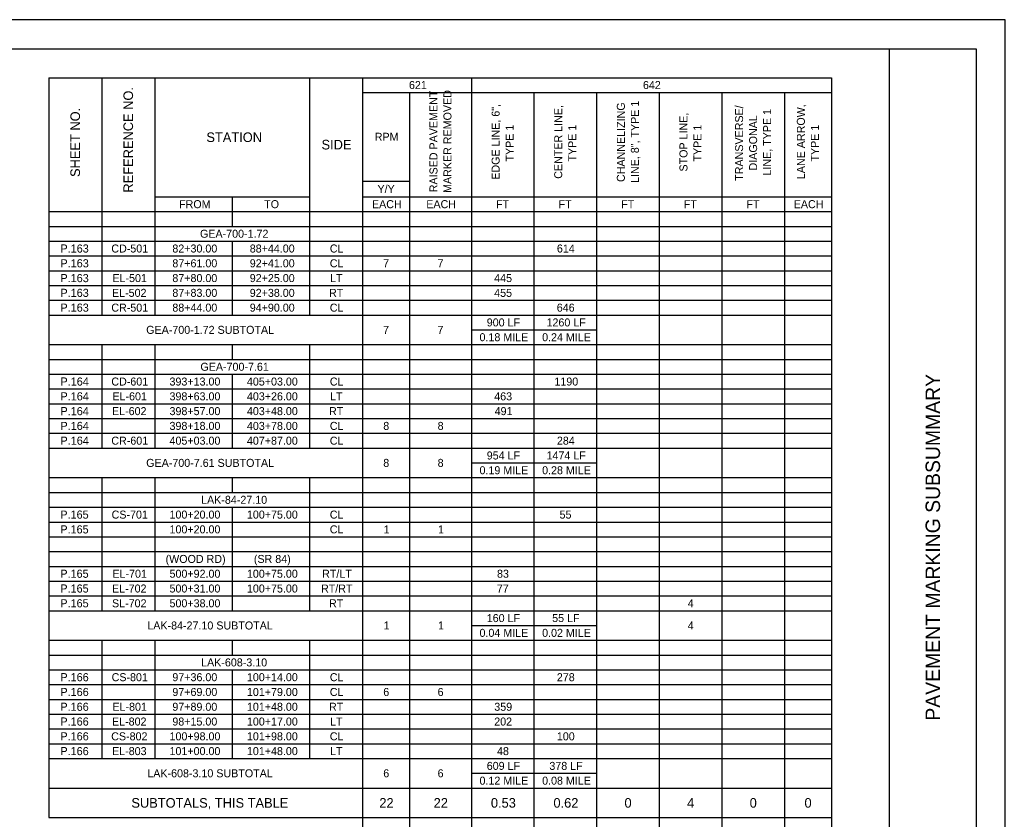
# Model space of a CAD drawing. Extents: x 0 to 34, y 0 to 22.
# Drawn here: x 17 to 34, y 8.21 to 22 of the extents above; entities that cross this region are included whole.
import ezdxf

# ---------------------------------------------------------------- set-up
doc = ezdxf.new("R2010")
doc.units = 0
for name, color, linetype in [('SH_Border', 7, 'Continuous'), ('SH_Cut_Line', 7, 'Continuous'), ('SH_Data', 7, 'Continuous'), ('SH_Text', 7, 'Continuous')]:
    doc.layers.add(name, color=color, linetype=linetype)

msp = doc.modelspace()

# ---------------------------------------------------------------- linework, layer by layer
at = {"layer": 'SH_Border'}
msp.add_line((32, 0.5), (32, 21.5), dxfattribs=at)
msp.add_lwpolyline([(1.5, 21.5), (33.5, 21.5), (33.5, 0.5), (1.5, 0.5)], close=True, dxfattribs=at)
at = {"layer": 'SH_Cut_Line'}
msp.add_lwpolyline([(0, 0), (34, 0), (34, 22), (0, 22)], close=True, dxfattribs=at)
at = {"layer": 'SH_Text'}
for p, q in [((17.5, 21), (31, 21)), ((17.5, 21), (17.5, 18.69)), ((18.415, 21), (18.415, 18.69)), ((19.33, 21), (19.33, 18.69)), ((22, 21), (22, 18.69)), ((22.915, 21), (22.915, 18.69)), ((24.79, 21), (24.79, 18.69)), ((31, 21), (31, 18.69)), ((22.915, 20.745), (31, 20.745)), ((23.725, 20.745), (23.725, 18.69)), ((25.87, 20.745), (25.87, 18.69)), ((26.95, 20.745), (26.95, 18.69)), ((28.03, 20.745), (28.03, 18.69)), ((29.11, 20.745), (29.11, 18.69)), ((30.19, 20.745), (30.19, 18.69)), ((22.915, 19.215), (23.725, 19.215)), ((19.33, 18.945), (22, 18.945)), ((20.665, 18.945), (20.665, 18.69)), ((22.915, 18.945), (31, 18.945)), ((17.5, 18.69), (31, 18.69)), ((17.5, 18.69), (31, 18.69)), ((17.5, 18.69), (17.5, 8.235)), ((18.415, 18.69), (18.415, 16.905)), ((19.33, 18.69), (19.33, 16.905)), ((20.665, 18.69), (20.665, 18.435)), ((22, 18.69), (22, 16.905)), ((22.915, 18.69), (22.915, 6.435)), ((23.725, 18.69), (23.725, 6.435)), ((24.79, 18.69), (24.79, 6.435)), ((25.87, 18.69), (25.87, 6.435)), ((26.95, 18.69), (26.95, 6.435)), ((28.03, 18.69), (28.03, 6.435)), ((29.11, 18.69), (29.11, 6.435)), ((30.19, 18.69), (30.19, 6.435)), ((31, 18.69), (31, 6.435)), ((17.5, 18.435), (31, 18.435)), ((17.5, 18.18), (31, 18.18)), ((20.665, 18.18), (20.665, 16.905)), ((17.5, 17.925), (31, 17.925)), ((17.5, 17.67), (31, 17.67)), ((17.5, 17.415), (31, 17.415)), ((17.5, 17.16), (31, 17.16)), ((17.5, 16.905), (31, 16.905)), ((24.79, 16.65), (26.95, 16.65)), ((17.5, 16.395), (31, 16.395)), ((18.415, 16.395), (18.415, 14.61)), ((19.33, 16.395), (19.33, 14.61)), ((20.665, 16.395), (20.665, 16.14)), ((22, 16.395), (22, 14.61)), ((17.5, 16.14), (31, 16.14)), ((17.5, 15.885), (31, 15.885)), ((20.665, 15.885), (20.665, 14.61)), ((17.5, 15.63), (31, 15.63)), ((17.5, 15.375), (31, 15.375)), ((17.5, 15.12), (31, 15.12)), ((17.5, 14.865), (31, 14.865)), ((17.5, 14.61), (31, 14.61)), ((24.79, 14.355), (26.95, 14.355)), ((17.5, 14.1), (31, 14.1)), ((18.415, 14.1), (18.415, 11.805)), ((19.33, 14.1), (19.33, 11.805)), ((20.665, 14.1), (20.665, 13.845)), ((22, 14.1), (22, 11.805)), ((17.5, 13.845), (31, 13.845)), ((17.5, 13.59), (31, 13.59)), ((20.665, 13.59), (20.665, 11.805)), ((17.5, 13.335), (31, 13.335)), ((17.5, 13.08), (31, 13.08)), ((17.5, 12.825), (31, 12.825)), ((17.5, 12.57), (31, 12.57)), ((17.5, 12.315), (31, 12.315)), ((17.5, 12.06), (31, 12.06)), ((17.5, 11.805), (31, 11.805)), ((24.79, 11.55), (26.95, 11.55)), ((17.5, 11.295), (31, 11.295)), ((18.415, 11.295), (18.415, 9.255)), ((19.33, 11.295), (19.33, 9.255)), ((20.665, 11.295), (20.665, 11.04)), ((22, 11.295), (22, 9.255)), ((17.5, 11.04), (31, 11.04)), ((17.5, 10.785), (31, 10.785)), ((20.665, 10.785), (20.665, 9.255)), ((17.5, 10.53), (31, 10.53)), ((17.5, 10.275), (31, 10.275)), ((17.5, 10.02), (31, 10.02)), ((17.5, 9.765), (31, 9.765)), ((17.5, 9.51), (31, 9.51)), ((17.5, 9.255), (31, 9.255)), ((24.79, 9), (26.95, 9)), ((17.5, 8.745), (31, 8.745)), ((17.5, 8.235), (22.915, 8.235)), ((22.915, 8.235), (31, 8.235))]:
    msp.add_line(p, q, dxfattribs=at)

# ---------------------------------------------------------------- texts
at = {"layer": 'SH_Data'}
msp.add_text('PAVEMENT MARKING SUBSUMMARY', height=0.25, rotation=90, dxfattribs=at).set_placement((32.875, 9.908))
at = {"layer": 'SH_Text'}
for s, height, p in [('621', 0.138, (23.714, 20.804)), ('642', 0.138, (27.75, 20.804)), ('STATION', 0.1656, (20.22, 19.89)), ('SIDE', 0.1656, (22.206, 19.762)), ('RPM', 0.138, (23.124, 19.911)), ('Y/Y', 0.138, (23.171, 19.011)), ('FROM', 0.138, (19.749, 18.749)), ('TO', 0.138, (21.217, 18.749)), ('EACH', 0.138, (23.076, 18.749)), ('EACH', 0.138, (24.013, 18.749)), ('FT', 0.138, (25.215, 18.749)), ('FT', 0.138, (26.295, 18.749)), ('FT', 0.138, (27.375, 18.749)), ('FT', 0.138, (28.455, 18.749)), ('FT', 0.138, (29.535, 18.749)), ('EACH', 0.138, (30.351, 18.749)), ('GEA-700-1.72', 0.138, (20.11, 18.239)), ('P.163', 0.14, (17.702, 17.983)), ('CD-501', 0.138, (18.58, 17.984)), ('82+30.00', 0.138, (19.633, 17.984)), ('88+44.00', 0.138, (20.968, 17.984)), ('CL', 0.138, (22.349, 17.984)), ('614', 0.138, (26.266, 17.984)), ('P.163', 0.14, (17.702, 17.728)), ('87+61.00', 0.138, (19.633, 17.729)), ('92+41.00', 0.138, (20.968, 17.729)), ('CL', 0.138, (22.349, 17.729)), ('7', 0.138, (23.268, 17.729)), ('7', 0.138, (24.206, 17.729)), ('P.163', 0.14, (17.702, 17.473)), ('EL-501', 0.138, (18.599, 17.474)), ('87+80.00', 0.138, (19.633, 17.474)), ('92+25.00', 0.138, (20.968, 17.474)), ('LT', 0.138, (22.354, 17.474)), ('445', 0.138, (25.184, 17.474)), ('P.163', 0.14, (17.702, 17.218)), ('EL-502', 0.138, (18.592, 17.219)), ('87+83.00', 0.138, (19.633, 17.219)), ('92+38.00', 0.138, (20.968, 17.219)), ('RT', 0.138, (22.335, 17.219)), ('455', 0.138, (25.184, 17.219)), ('P.163', 0.14, (17.702, 16.963)), ('CR-501', 0.138, (18.58, 16.964)), ('88+44.00', 0.138, (19.633, 16.964)), ('94+90.00', 0.138, (20.968, 16.964)), ('CL', 0.138, (22.349, 16.964)), ('646', 0.138, (26.264, 16.964)), ('900 LF', 0.138, (25.056, 16.709)), ('1260 LF', 0.138, (26.087, 16.709)), ('GEA-700-1.72 SUBTOTAL', 0.138, (19.182, 16.581)), ('7', 0.138, (23.268, 16.581)), ('7', 0.138, (24.206, 16.581)), ('0.18 MILE', 0.138, (24.931, 16.454)), ('0.24 MILE', 0.138, (26.011, 16.454)), ('GEA-700-7.61', 0.138, (20.117, 15.944)), ('P.164', 0.14, (17.703, 15.688)), ('CD-601', 0.138, (18.58, 15.689)), ('393+13.00', 0.138, (19.584, 15.689)), ('405+03.00', 0.138, (20.919, 15.689)), ('CL', 0.138, (22.349, 15.689)), ('1190', 0.138, (26.223, 15.689)), ('P.164', 0.14, (17.703, 15.433)), ('EL-601', 0.138, (18.599, 15.434)), ('398+63.00', 0.138, (19.584, 15.434)), ('403+26.00', 0.138, (20.919, 15.434)), ('LT', 0.138, (22.354, 15.434)), ('463', 0.138, (25.185, 15.434)), ('P.164', 0.14, (17.703, 15.178)), ('EL-602', 0.138, (18.592, 15.179)), ('398+57.00', 0.138, (19.584, 15.179)), ('403+48.00', 0.138, (20.919, 15.179)), ('RT', 0.138, (22.335, 15.179)), ('491', 0.138, (25.192, 15.179)), ('P.164', 0.14, (17.703, 14.923)), ('398+18.00', 0.138, (19.584, 14.924)), ('403+78.00', 0.138, (20.919, 14.924)), ('CL', 0.138, (22.349, 14.924)), ('8', 0.138, (23.271, 14.924)), ('8', 0.138, (24.209, 14.924)), ('P.164', 0.14, (17.703, 14.668)), ('CR-601', 0.138, (18.58, 14.669)), ('405+03.00', 0.138, (19.584, 14.669)), ('407+87.00', 0.138, (20.919, 14.669)), ('CL', 0.138, (22.349, 14.669)), ('284', 0.138, (26.266, 14.669)), ('954 LF', 0.138, (25.056, 14.414)), ('1474 LF', 0.138, (26.087, 14.414)), ('GEA-700-7.61 SUBTOTAL', 0.138, (19.182, 14.286)), ('8', 0.138, (23.271, 14.286)), ('8', 0.138, (24.209, 14.286)), ('0.19 MILE', 0.138, (24.931, 14.159)), ('0.28 MILE', 0.138, (26.011, 14.159)), ('LAK-84-27.10', 0.138, (20.129, 13.649)), ('P.165', 0.14, (17.7, 13.393)), ('CS-701', 0.138, (18.585, 13.394)), ('100+20.00', 0.138, (19.584, 13.394)), ('100+75.00', 0.138, (20.919, 13.394)), ('CL', 0.138, (22.349, 13.394)), ('55', 0.138, (26.312, 13.394)), ('P.165', 0.14, (17.7, 13.138)), ('100+20.00', 0.138, (19.584, 13.139)), ('CL', 0.138, (22.349, 13.139)), ('1', 0.138, (23.278, 13.139)), ('1', 0.138, (24.216, 13.139)), ('(WOOD RD)', 0.138, (19.516, 12.629)), ('(SR 84)', 0.138, (21.039, 12.629)), ('P.165', 0.14, (17.7, 12.373)), ('EL-701', 0.138, (18.599, 12.374)), ('500+92.00', 0.138, (19.584, 12.374)), ('100+75.00', 0.138, (20.919, 12.374)), ('RT/LT', 0.138, (22.216, 12.374)), ('83', 0.138, (25.233, 12.374)), ('P.165', 0.14, (17.7, 12.118)), ('EL-702', 0.138, (18.592, 12.119)), ('500+31.00', 0.138, (19.584, 12.119)), ('100+75.00', 0.138, (20.919, 12.119)), ('RT/RT', 0.138, (22.197, 12.119)), ('77', 0.138, (25.23, 12.119)), ('P.165', 0.14, (17.7, 11.863)), ('SL-702', 0.138, (18.592, 11.864)), ('500+38.00', 0.138, (19.584, 11.864)), ('RT', 0.138, (22.335, 11.864)), ('4', 0.138, (28.523, 11.864)), ('160 LF', 0.138, (25.056, 11.609)), ('55 LF', 0.138, (26.184, 11.609)), ('LAK-84-27.10 SUBTOTAL', 0.138, (19.201, 11.481)), ('1', 0.138, (23.278, 11.481)), ('1', 0.138, (24.216, 11.481)), ('4', 0.138, (28.523, 11.481)), ('0.04 MILE', 0.138, (24.931, 11.354)), ('0.02 MILE', 0.138, (26.011, 11.354)), ('LAK-608-3.10', 0.138, (20.129, 10.844)), ('P.166', 0.14, (17.701, 10.588)), ('CS-801', 0.138, (18.585, 10.589)), ('97+36.00', 0.138, (19.633, 10.589)), ('100+14.00', 0.138, (20.919, 10.589)), ('CL', 0.138, (22.349, 10.589)), ('278', 0.138, (26.265, 10.589)), ('P.166', 0.14, (17.701, 10.333)), ('97+69.00', 0.138, (19.633, 10.334)), ('101+79.00', 0.138, (20.919, 10.334)), ('CL', 0.138, (22.349, 10.334)), ('6', 0.138, (23.271, 10.334)), ('6', 0.138, (24.208, 10.334)), ('P.166', 0.14, (17.701, 10.078)), ('EL-801', 0.138, (18.599, 10.079)), ('97+89.00', 0.138, (19.633, 10.079)), ('101+48.00', 0.138, (20.919, 10.079)), ('RT', 0.138, (22.335, 10.079)), ('359', 0.138, (25.186, 10.079)), ('P.166', 0.14, (17.701, 9.823)), ('EL-802', 0.138, (18.592, 9.824)), ('98+15.00', 0.138, (19.633, 9.824)), ('100+17.00', 0.138, (20.919, 9.824)), ('LT', 0.138, (22.354, 9.824)), ('202', 0.138, (25.185, 9.824)), ('P.166', 0.14, (17.701, 9.568)), ('CS-802', 0.138, (18.578, 9.569)), ('100+98.00', 0.138, (19.584, 9.569)), ('101+98.00', 0.138, (20.919, 9.569)), ('CL', 0.138, (22.349, 9.569)), ('100', 0.138, (26.265, 9.569)), ('P.166', 0.14, (17.701, 9.313)), ('EL-803', 0.138, (18.593, 9.314)), ('101+00.00', 0.138, (19.584, 9.314)), ('101+48.00', 0.138, (20.919, 9.314)), ('LT', 0.138, (22.354, 9.314)), ('48', 0.138, (25.233, 9.314)), ('609 LF', 0.138, (25.056, 9.059)), ('378 LF', 0.138, (26.136, 9.059)), ('LAK-608-3.10 SUBTOTAL', 0.138, (19.201, 8.931)), ('6', 0.138, (23.271, 8.931)), ('6', 0.138, (24.208, 8.931)), ('0.12 MILE', 0.138, (24.931, 8.804)), ('0.08 MILE', 0.138, (26.011, 8.804)), ('SUBTOTALS, THIS TABLE', 0.1656, (18.926, 8.407)), ('22', 0.1656, (23.203, 8.407)), ('22', 0.1656, (24.14, 8.407)), ('0.53', 0.1656, (25.127, 8.407)), ('0.62', 0.1656, (26.206, 8.407)), ('0', 0.166, (27.431, 8.407)), ('4', 0.166, (28.512, 8.407)), ('0', 0.166, (29.591, 8.407)), ('0', 0.166, (30.536, 8.407))]:
    msp.add_text(s, height=height, dxfattribs=at).set_placement(p)
for s, height, p in [('REFERENCE NO.', 0.1656, (18.955, 19.018)), ('RAISED PAVEMENT ', 0.138, (24.206, 19.023)), ('MARKER REMOVED', 0.138, (24.447, 19.012)), ('LINE, 8", TYPE 1', 0.138, (27.68, 19.184)), ('SHEET NO.', 0.1656, (18.04, 19.287)), ('EDGE LINE, 6",', 0.138, (25.278, 19.24)), ('CENTER LINE,', 0.138, (26.358, 19.256)), ('CHANNELIZING ', 0.138, (27.438, 19.2)), ('TRANSVERSE/', 0.138, (29.477, 19.221)), ('LINE, TYPE 1', 0.138, (29.96, 19.312)), ('LANE ARROW,', 0.138, (30.543, 19.25)), ('STOP LINE,', 0.138, (28.518, 19.381)), ('DIAGONAL', 0.138, (29.719, 19.399)), ('TYPE 1', 0.138, (25.52, 19.553)), ('TYPE 1', 0.138, (26.6, 19.553)), ('TYPE 1', 0.138, (28.76, 19.553)), ('TYPE 1', 0.138, (30.785, 19.553))]:
    msp.add_text(s, height=height, rotation=90, dxfattribs=at).set_placement(p)

doc.saveas('drawing.dxf')
